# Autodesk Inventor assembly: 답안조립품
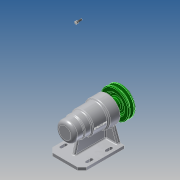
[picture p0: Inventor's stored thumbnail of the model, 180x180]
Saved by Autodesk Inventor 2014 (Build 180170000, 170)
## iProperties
Created: 2017-09
Part Number: 답안조립품
Document SubType Name: Assembly
Designer: kb542-22
Author: kb542-22
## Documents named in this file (10)
- C:\Users\kb542-22\Desktop\470907V1021\답안조립품.iam
- C:\Users\kb542-22\Desktop\470907V1021\1-본체.ipt
- C:\Users\kb542-22\Desktop\470907V1021\축.ipt
- C:\Users\kb542-22\Desktop\470907V1021\키 5 x 5 x 16.ipt
- C:\Users\kb542-22\Desktop\470907V1021\베어링 6004.ipt
- C:\Users\kb542-22\Desktop\470907V1021\V벨트풀리.ipt
- C:\Users\kb542-22\Desktop\470907V1021\멈춤나사 M3x8.ipt
- C:\Users\kb542-22\Desktop\470907V1021\어댑터슬리브.ipt
- C:\Users\kb542-22\Desktop\470907V1021\베어링 51202.ipt
- C:\Users\kb542-22\Desktop\470907V1021\볼트 M4 x 12.ipt
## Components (2 placed, 2 different names)
1. 1-본체:1
2. V벨트풀리:1
